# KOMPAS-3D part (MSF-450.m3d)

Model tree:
1. Ось X
2. Ось Y
3. Ось Z
4. Начало координат  (labels: Операция без истории:1)

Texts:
  Линия-выноска #1
  Линия-выноска #2
  Линия-выноска #3
  Отклонения формы и база
  Марка координационной оси
  Марка/позиционное обозначение с линией-выноской
  Марка/позиционное обозначение на линии
  Марка/позиционное обозначение без линии-выноски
